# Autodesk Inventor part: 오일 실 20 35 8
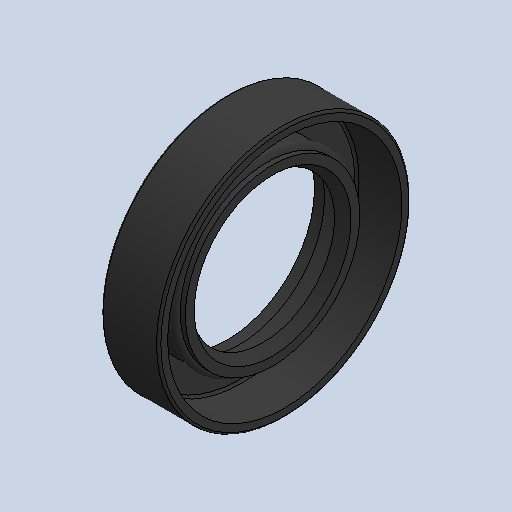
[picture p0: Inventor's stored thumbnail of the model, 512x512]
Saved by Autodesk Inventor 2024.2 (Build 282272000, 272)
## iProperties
Created: 2026-01
Part Number: 오일 실 20 35 8
Material: 고무
Description: 오일-실
Document SubType Name: Modeling
Designer: home
Density: 0.93 g/cm^3
Appearance: 기본값
Author: jhkim
Sending System: Autodesk Inventor 2026
Preprocessor: ST-DEVELOPER v20.1
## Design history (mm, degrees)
feature "Solid1"
node "솔리드1"
